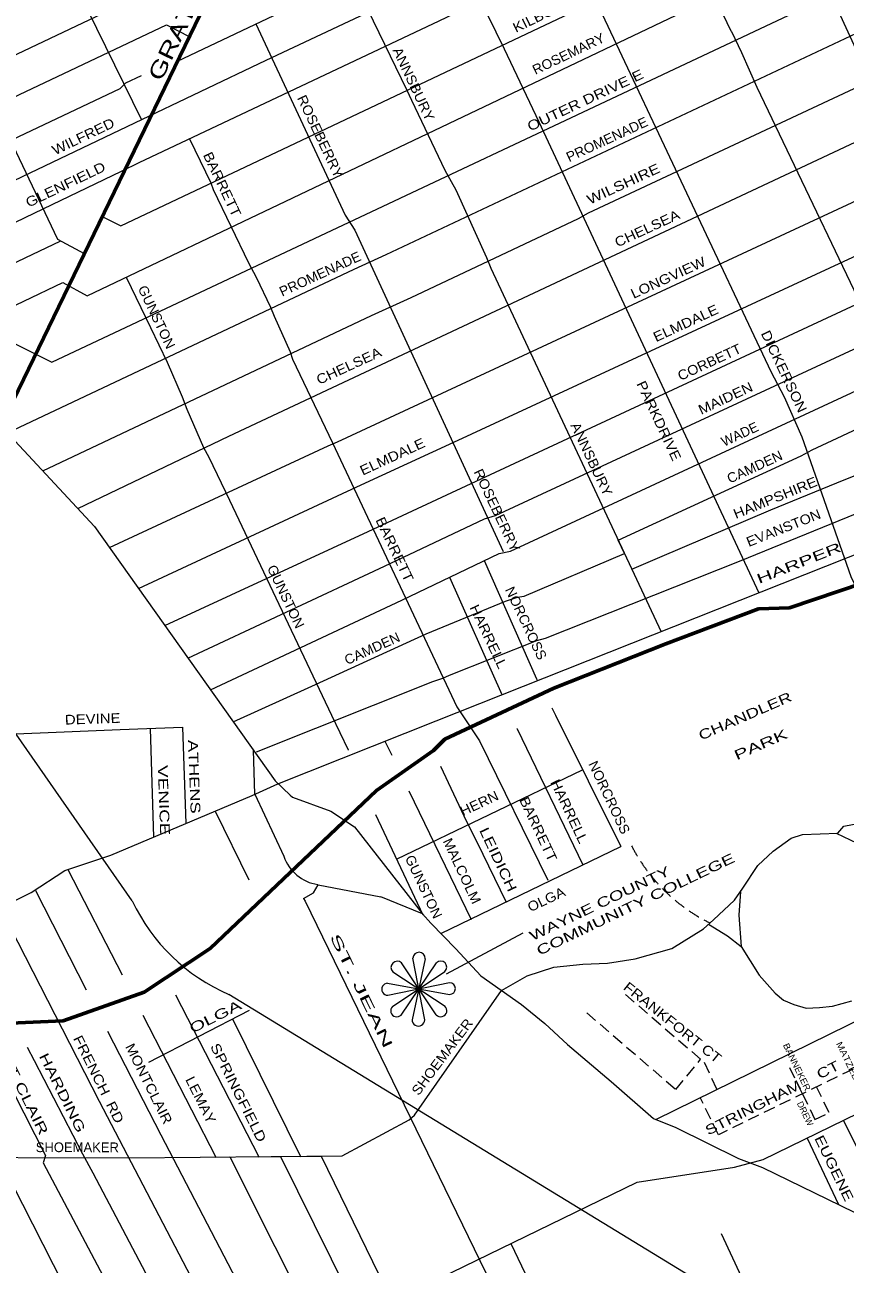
# Model space of a CAD drawing. Extents: x 34705 to 138605, y 34275 to 143551.
# Drawn here: x 113481 to 119808, y 120262 to 129823 of the extents above; entities that cross this region are included whole.
import ezdxf
from ezdxf.enums import TextEntityAlignment as Align

# ---------------------------------------------------------------- set-up
doc = ezdxf.new("R2010")
doc.units = 0
doc.header["$LTSCALE"] = 30
doc.linetypes.add('MEDIUM_DASHED', pattern=[4.5, 3, -1.5])
for name, color, linetype, lineweight in [('1', 7, 'Continuous', 13), ('11', 7, 'Continuous', 13), ('3', 7, 'Continuous', 13), ('50', 7, 'Continuous', 13), ('51', 7, 'Continuous', 35)]:
    doc.layers.add(name, color=color, linetype=linetype, lineweight=lineweight)

msp = doc.modelspace()

# ---------------------------------------------------------------- linework, layer by layer
at = {"layer": '1'}
for p, q in [((116755.42, 125560.55), (117160.43, 124657.18)), ((114448.08, 124395.42), (114473.12, 123556.38)), ((114698.47, 124405.86), (114722.27, 123661.73)), ((116258.49, 124296.27), (116310.6, 124188.4)), ((115254.35, 123887.35), (115244.15, 124226.21)), ((116347.69, 123387.37), (117783.21, 124076.65)), ((116443.32, 123913.7), (116922.95, 122920.93)), ((115254.35, 123887.35), (115479.34, 123408.64)), ((114949.04, 123757.61), (115207.69, 123227.81)), ((116185.04, 123730.28), (116552.13, 122956.37)), ((116690.38, 122813.88), (118077.72, 123484.05)), ((113814.03, 123307.24), (114231.65, 122495.29)), ((113563.24, 123146.07), (113955.21, 122378.93)), ((114437.67, 121821.56), (115213.51, 122222.36)), ((119794.08, 121370.72), (120072.42, 120808.06)), ((119514.23, 121234.18), (119755.76, 120723.33))]:
    msp.add_line(p, q, dxfattribs=at)
at = {"layer": '1', "linetype": 'MEDIUM_DASHED'}
for p, q in [((117815.28, 122201.75), (118503.35, 121608.85)), ((118503.35, 121608.85), (118692.81, 121843.04)), ((119478.21, 121576.44), (119380.52, 121776.68))]:
    msp.add_line(p, q, dxfattribs=at)
at = {"layer": '1', "lineweight": 53}
msp.add_lwpolyline([(101368.9, 103017.54), (102548.84, 105055.11), (103212.24, 106184.42), (103282.07, 106324.13), (104294.63, 108304.78), (105138.43, 110039.49), (106145.17, 112117.65), (109289.05, 118526.78), (110743.87, 121478.11), (113275.26, 126686.61), (116465.7, 133274.74), (120395.18, 141348.71), (121157.51, 142914.61), (121243.66, 143093.14)], dxfattribs=at)
at = {"layer": '1'}
for points in [[(113828.8, 142881.64), (113908.05, 140286.22), (113913.86, 140181.52), (113989.46, 137633.88), (114001.09, 137546.63), (114123.19, 133520.13), (114158.08, 133438.7), (115742.57, 131946.76), (115893.76, 131970.03), (116108.9, 131847.88), (116858.99, 130289.04), (117178.8, 129637.59), (117446.27, 129073.38), (119143.14, 125441.86)], [(112413.12, 135252.27), (112419.49, 134940.82), (112407.87, 134853.57), (112487.81, 132851.23), (112555.76, 132711.83), (112628.32, 132747.22), (112750.93, 132473.15), (113175.4, 131594.85), (113216.1, 131519.24), (113727.8, 130446.09), (113756.87, 130364.66), (114380.05, 129090.06)], [(117019.74, 133007.29), (117040.09, 131765.86), (117934.55, 129905.56), (119235.82, 127149.24), (119336.89, 126952.09), (119473.34, 126643.73), (119851.09, 125566.98), (121478.31, 122254.59), (121549.06, 122178.76), (122869.28, 119400.96), (123384.74, 118354.54), (125383.29, 114242.35)], [(111509.73, 132520.15), (111657.77, 132426.62), (111721.73, 132374.27), (111791.51, 132252.12), (113733.61, 128168.91), (113939.82, 128058.9)], [(111388.95, 128630.48), (111591.31, 128731.69), (112199.45, 129022.83), (113089.94, 129448.66), (113168.13, 129479.08), (114942.6, 130319.89), (115159.79, 130211.26), (115789.65, 130502.39), (119505.83, 132275.26)], [(114657.99, 129541.89), (118932.44, 131571.33), (119006.28, 131601.74), (119653.52, 131910.26), (120250.8, 132205.74), (122306.69, 132245.12)], [(118640.45, 132236.99), (118947.91, 131597.77), (118976.98, 131539.6), (119070.01, 131341.84), (119110.72, 131254.59), (119192.12, 131084.45), (119221.19, 131010.29), (119680.55, 130073.83), (119738.7, 129963.31), (120023.62, 129343.86), (120895.82, 127529.09), (121424.96, 126396.32), (121535.43, 126349.79), (121580.04, 126258.34)], [(117784.51, 132160.52), (118927.56, 129777.18), (118930.46, 129771.37), (119008.96, 129608.5), (119128.16, 129340.94), (120163.17, 127175.74), (120291.09, 126850.01), (120500.42, 126320.7), (120605.09, 126058.96), (120610.9, 125977.53), (120655.3, 125888.69)], [(112840.5, 128350.56), (113029.13, 128444.9), (113463.52, 128653.48), (114330.11, 129066.28), (115342.23, 129548.61), (116835.44, 130253.62), (117564.12, 130602.33), (120368.08, 131927.64), (122067.69, 131958.71)], [(109137.12, 131674.83), (109369.7, 131394.19), (109596.48, 131080.09), (109770.92, 130812.53), (109968.62, 130498.44), (110189.57, 130143.63), (110387.27, 129835.35), (110573.34, 129538.7), (110701.26, 129381.66), (111026.89, 129015.21), (111404.84, 128613.87), (113227.73, 126708.96), (113338.21, 126685.69), (114018.53, 125952.8), (115411.14, 123991.18), (115527.43, 123880.66), (115544.77, 123865.42)], [(112242.46, 127738.56), (112493.21, 127860.75), (113690.88, 128437.04), (114226.55, 128694.85), (114363, 128760.57), (116677.5, 129852.48), (118426, 130690.37), (118552.34, 130735.87), (119936.99, 131403.15), (120376.65, 131620.52), (122075.94, 131656.69)], [(114077.47, 128343.14), (114221.52, 128271.09), (120094.42, 131054.24), (120633.06, 131036.86), (121119.57, 131019.48), (121423.64, 131023.82), (121506.17, 131028.17), (122010.06, 131032.51), (122091.39, 131029.44)], [(115691.04, 130834.8), (116428.71, 129317.68), (116463.59, 129242.06), (116719.44, 128701.12), (116806.66, 128549.89), (117040.69, 128027.86), (117075.58, 127946.42), (118387.98, 125140.52)], [(112662.87, 127299.24), (112868.41, 127402.04), (113774.1, 127835.49), (113960.89, 127732.28), (120307.27, 130758.76), (120750.34, 130741.38), (121167.35, 130719.65), (121393.23, 130715.31), (122101.59, 130718.5)], [(117156.53, 122373.91), (117354.34, 122487.31), (117562.04, 122553.07), (117785.51, 122576.74), (117974.81, 122584.64), (118187.76, 122618.83), (118471.9, 122697.65), (118716.31, 122849), (118791.96, 122918.86), (118954.9, 123070.21), (119018.91, 123163.34), (119135.3, 123337.98), (119251.69, 123448.58), (119391.35, 123547.54), (119478.64, 123576.65), (119752.14, 123588.29), (119798.7, 123640.68), (119973.28, 123675.61), (120118.76, 123757.1), (125265.94, 126298.05), (133709.74, 130483.48)], [(112854.63, 127098.85), (113375.55, 127377.06), (113688.31, 127220.63), (120428.89, 130395.93), (122118.66, 130309.03), (123063.45, 129791.94), (123162.27, 127218.46), (123379.46, 126788.28)], [(113348.12, 126675.01), (116020.97, 127937.6), (116268.57, 128050.57), (120507.08, 130048.31), (121532.24, 129996.17), (122123, 129922.3), (122867.97, 129505.15), (123074.46, 129505.15)], [(111601.27, 128408.6), (111804.16, 128510.08), (114573.37, 129822.36), (114749.79, 129731.45)], [(115262.39, 129828.85), (115951.9, 128355.04), (116027.49, 128238.71), (117171.66, 125760.32)], [(113620.9, 126381.15), (116155.63, 127581.28), (116459.7, 127720.33), (117750.9, 128328.67), (117829.09, 128372.12), (120724.28, 129726.76), (120767.72, 129731.11), (121532.24, 129692), (122132.49, 129621.36)], [(97901.79, 110686.48), (98842.55, 111139.22), (98862.73, 111098.07), (107780.39, 115477.93), (107908.41, 115576.89), (108065.53, 115629.28), (109209.03, 116179.38), (109744.4, 116470.44), (111059.56, 117168.98), (111717.14, 117524.08), (112237.97, 117804.95), (112528.94, 117956.3), (112895.56, 118183.33), (114356.2, 118957.54), (115440.05, 119549.85), (118204.21, 120894.54), (118954.9, 121010.96), (119176.03, 121069.18), (124515.25, 123674.15), (127785.69, 125298.26), (131565.33, 127169.77), (132886.31, 127821.74), (134611.73, 128667.27), (136181.01, 129472.15)], [(111812.18, 128188.2), (112021.35, 128292.82), (114217.17, 129331.34), (114260.61, 129374.79), (114382.24, 129431.28)], [(113889.29, 126092.03), (115055.54, 126649.23), (120896.94, 129393.26), (120909.98, 129436.72), (122144.83, 129313.63)], [(114134.53, 125789.4), (115820.06, 126575.36), (115893.91, 126605.77), (121183.64, 129067.37), (122156.67, 129018.7)], [(114750.34, 128943.31), (114916.89, 128603.7), (114934.34, 128551.35), (115207.62, 127987.14), (115265.77, 127876.63), (115376.25, 127643.96), (115405.32, 127574.16), (115527.43, 127300.79), (115544.88, 127242.62), (115853.05, 126596.98), (116812.47, 124561.2), (116986.91, 124299.46), (117516.05, 123223.39)], [(114358.82, 125473.48), (116041.6, 126258.15), (116823.49, 126618.81), (121353.05, 128719.75), (121587.62, 128698.02), (122121.91, 128724.09), (122217.48, 128741.47), (124206.86, 128816.28)], [(115267.3, 124213.7), (116626.93, 124756.86), (116705.12, 124782.93), (116757.25, 124804.66), (117430.55, 125074.07), (117495.7, 125091.45), (118992.16, 125685.66), (120473.15, 126288.7), (122030.69, 126904.51), (122195.76, 126974.03), (124530.58, 127886.54), (124621.81, 127925.65), (126181.25, 128412.32), (126237.72, 128442.74), (126774.51, 128701.62)], [(114560.02, 125190.06), (116128.47, 125914.87), (116962.5, 126301.6), (121448.61, 128389.51), (122182.63, 128371.71)], [(112450.16, 127521.52), (112655.56, 127632.34), (113759.25, 128155.23)], [(114913.21, 124692.56), (116389.11, 125384.75), (117140.6, 125745.41), (117227.47, 125762.79), (121622.37, 127802.89), (121717.93, 127863.73), (122178.38, 128085.34), (123838.82, 128141.82), (124181.99, 128146.17), (124529.5, 128159.21), (124616.37, 128167.9), (125128.95, 128176.59), (125437.36, 128185.28)], [(108436.9, 121413.01), (109494.34, 121968.63), (109634.95, 122036.15), (111021.43, 122424.37), (111122.67, 122413.12), (111499.52, 122480.64), (112180.11, 122643.81), (112478.21, 122722.58), (112743.97, 122776.02), (112884.59, 122809.78), (113267.07, 123001.08), (113531.43, 123130.49), (113790.16, 123299.29), (114144.51, 123417.44), (115235.7, 123878.81), (115432.56, 123968.84), (116653.11, 124452.72), (124173.08, 127439.91), (124643.06, 127626.95), (126069.8, 128061.11)], [(114738.96, 124938.01), (116254.45, 125645.47), (117027.65, 126010.47), (117110.19, 126036.54), (121524.64, 128086.42)], [(114262.97, 127876.34), (114451.72, 127486.92), (114579.64, 127219.35), (114695.93, 126951.79), (114730.82, 126858.73), (114858.74, 126562.08), (114899.45, 126486.47), (115059.36, 126156.38), (115847.24, 124497.22), (115975.16, 124229.66), (115975.49, 124227.34)], [(115088.43, 124445.74), (115694.09, 124719.92), (116575.89, 125124.03), (117188.38, 125376.06), (117280.68, 125406.48), (117332.81, 125415.17), (118105.73, 125743.96), (118057.85, 125846.34), (119469.99, 126497.14), (119552.52, 126543.85), (121739.65, 127563.9), (121813.5, 127611.7), (122205.52, 127801.17)], [(118346.91, 121379.51), (124443.96, 124372.69), (124590.9, 124476.02), (131269.97, 127786.78)], [(118161.62, 125624.47), (118379.68, 125716.08), (119235.42, 126081.08), (119800.12, 126311.38), (121230.23, 126879.03), (122221.82, 127282.55)], [(111762.44, 126050.24), (112274.13, 125363.89), (112811.98, 124651.35), (112849.78, 123927.2), (113291.7, 123043.08), (113314.95, 122967.46), (114053.42, 121519.14), (116755.93, 116340.18)], [(117024.92, 125689.89), (117428.83, 124776.41), (117435.99, 124762.66)], [(117544.88, 124553.53), (117574.2, 124497.22), (118077.72, 123484.05)], [(112117.66, 124304.76), (112791.96, 124331.53), (112915.16, 124331.53), (114216.23, 124385.76), (114698.47, 124405.86)], [(117276.9, 124394.2), (117277.65, 124392.52), (117784.78, 123342.54)], [(116686.71, 124103.61), (116888.06, 123677.08), (116969.47, 123514.22), (117190.43, 123060.53)], [(115544.77, 123865.42), (115840.84, 123757.6), (116023.1, 123635.96), (116547.19, 122963.87), (116225.77, 123094.95)], [(119738.12, 123587.69), (119901.51, 123509.86), (119988.73, 123457.51), (120087.58, 123352.81), (120180.62, 123224.85), (120285.28, 123021.27), (120331.8, 122806.06), (120325.98, 122742.08)], [(115631.77, 123084.32), (115708.82, 123125.83), (115742.7, 123189.57), (116225.77, 123094.95)], [(115631.77, 123084.32), (115642.27, 123061.99), (121617.28, 110770.39)], [(119001, 123136.46), (118987.45, 122953.47), (119006.05, 122712.99)], [(116547.19, 122963.87), (116613.32, 122893.31), (116805.2, 122695.54), (116997.09, 122486.15), (117311.08, 122265.12), (117491.33, 122119.7), (117665.77, 121956.84), (118003.03, 121671.83), (118328.65, 121386.82), (118503.09, 121317.02), (118985.7, 121078.54), (119171.77, 121008.74), (120379.77, 120418.37), (120967.05, 119644.76)], [(118755.23, 122884.94), (118901.39, 122794.42), (119006.05, 122712.99), (119145.6, 122491.96), (119267.71, 122352.37), (119331.67, 122300.02), (119413.08, 122265.12), (119506.11, 122236.03), (119610.78, 122241.85), (119709.63, 122253.48), (119860.81, 122294.2)], [(110898.74, 121088.09), (112569.67, 121088.09), (114286.37, 121082.27), (115928.87, 121096.83), (116446.78, 121376.24), (116487.52, 121411.17), (117156.53, 122373.91)], [(114643.86, 122339.84), (115286.41, 121091.13), (115453.06, 121092.61), (117537.85, 116881.91), (117578.55, 116788.85), (119695.09, 112413.35), (119747.43, 112308.65)], [(114392, 122183.52), (114955.37, 121088.2), (115063.4, 121089.16), (115757.37, 119708.21)], [(115082.68, 122154.76), (115607.11, 121093.98), (115765.73, 121095.38), (116310.96, 119976.31), (116363.29, 119877.43), (117113.38, 118336.04), (117798.89, 116979.24)], [(114118.64, 122060.38), (114530.22, 121258.85), (115403.87, 119580.78), (117000.35, 116492.9), (116968.79, 116473.73), (116930.86, 116449.93), (119190.33, 112040.04), (119249.32, 112077.95), (120257.44, 110107.32)], [(112894.44, 121929.17), (113280.07, 121136.71), (113303.32, 121037.82), (114332.52, 119016.58), (114384.85, 118935.14), (115124.76, 117466.47), (115153.84, 117385.04), (115915.56, 115866.92), (115979.52, 115808.75), (118244.33, 111511.78), (118360.62, 111453.62), (119805.57, 108692.21)], [(113220.39, 121920.32), (113640.58, 121101.81), (113623.13, 121043.64), (114618.89, 119164.9), (116241.18, 116041.41), (116281.88, 115983.25), (117113.38, 114415.69), (118526.35, 111686.28), (118604.84, 111577.22), (119553.33, 109764.96)], [(113499.83, 121937.03), (113553.36, 121834.69), (113925.49, 121113.44), (114006.9, 120968.02), (116520.26, 116192.32), (116594.39, 116238.83), (118853.58, 111823.61), (118799.46, 111788.83), (119797.02, 109882.81)], [(118851.97, 120498.34), (119008.96, 120160.98), (119749.65, 118638.14)], [(117229.8, 120421.68), (117585.07, 119678.93), (117625.68, 119634.85), (118636.88, 117539.82)]]:
    msp.add_lwpolyline(points, dxfattribs=at)
at = {"layer": '1', "linetype": 'MEDIUM_DASHED'}
for points in [[(118113.7, 122342.87), (118720.62, 121819.72), (118818.01, 121611.27)], [(121082.25, 122359.04), (118830.23, 121260.3), (118690.32, 121547.06)], [(119478.21, 121576.44), (119574.69, 121378.69), (119684.06, 121432.05), (119587.57, 121629.8)]]:
    msp.add_lwpolyline(points, dxfattribs=at)
msp.add_arc((119362.03, 124105.9), 1350.27, 207.20903, 243.78591, dxfattribs=at)
at = {"layer": '1'}
msp.add_arc((115786.71, 123512.04), 324.29, 198.59424, 261.80515, dxfattribs=at)
at = {"layer": '3'}
for p, q in [((117322.43, 122814.43), (116730.95, 122498.67)), ((117322.43, 122814.43), (116730.95, 122498.67)), ((116383.36, 122183.87), (116655.8, 122587.15)), ((116383.36, 122183.87), (116655.8, 122587.15)), ((116653.09, 122185.28), (116386.44, 122585.64)), ((116653.09, 122185.28), (116386.44, 122585.64)), ((116386.88, 122584.64), (116387.6, 122585.36)), ((116386.88, 122584.64), (116387.6, 122585.36)), ((116569.34, 122618.35), (116467.81, 122148.02)), ((116569.34, 122618.35), (116467.81, 122148.02)), ((116565.79, 122147.71), (116473.27, 122623.73)), ((116565.79, 122147.71), (116473.27, 122623.73)), ((116316.06, 122249.76), (116721.27, 122519.65)), ((116316.06, 122249.76), (116721.27, 122519.65)), ((116318.83, 122517.66), (116721.92, 122253.64)), ((116318.83, 122517.66), (116721.92, 122253.64)), ((116319.46, 122516.64), (116320.19, 122517.38)), ((116319.46, 122516.64), (116320.19, 122517.38)), ((116279.07, 122429.19), (116756.96, 122342.49)), ((116279.07, 122429.19), (116756.96, 122342.49)), ((116280.04, 122336.96), (116756.02, 122434.12)), ((116280.04, 122336.96), (116756.02, 122434.12))]:
    msp.add_line(p, q, dxfattribs=at)
for centre, radius, start, end in [((116521.14, 122620.09), 48.1, 357.90544, 177.31124), ((116521.14, 122620.09), 48.1, 357.90544, 177.31124), ((116353.38, 122551.33), 48.02, 45.54578, 225.33734), ((116353.38, 122551.33), 48.02, 45.54578, 225.33734), ((116688.5, 122553.3), 46.65, 314.26963, 133.99655), ((116688.5, 122553.3), 46.65, 314.26963, 133.99655), ((116279.4, 122383.16), 45.88, 90.42817, 271.25269), ((116279.4, 122383.16), 45.88, 90.42817, 271.25269), ((116756.88, 122388.41), 45.43, 270.57171, 90.10109), ((116756.88, 122388.41), 45.43, 270.57171, 90.10109), ((116756.88, 122388.41), 45.43, 270.54777, 270.57171), ((116756.88, 122388.41), 45.43, 270.54777, 270.57171), ((116349.74, 122217.03), 46.64, 135.13004, 315.42051), ((116349.74, 122217.03), 46.64, 135.13004, 315.42051), ((116687.92, 122218.71), 48.38, 224.62256, 46.0351), ((116687.92, 122218.71), 48.38, 224.62256, 46.0351), ((116516.68, 122147.77), 48.9, 178.86395, 0.59288), ((116516.68, 122147.77), 48.9, 178.86395, 0.59288)]:
    msp.add_arc(centre, radius, start, end, dxfattribs=at)
at = {"layer": '50'}
for p, q in [((114310.06, 123063.91), (112665.98, 125417.47)), ((118804.69, 120050.59), (115055.23, 122343.49))]:
    msp.add_line(p, q, dxfattribs=at)
msp.add_arc((115633.79, 123687.52), 1463.26, 205.22512, 246.70955, dxfattribs=at)
at = {"layer": '51', "lineweight": 60}
msp.add_lwpolyline([(107292.97, 119950.63), (110456.13, 121661.99), (111429.48, 121939.01), (111860.26, 122053.92), (113776.21, 122140.11), (114400.84, 122360.69), (114909.57, 122697.22), (116193.7, 123916.11), (116632.69, 124223.91), (116719.86, 124312.14), (117560.91, 124706.13), (118426.27, 125047.42), (119140.77, 125316.55), (119378.93, 125325.38), (119948.67, 125518.72), (120494.32, 125699.29), (120946.63, 125836.77), (121127.15, 125840.88), (124848.27, 127379.88), (125296.48, 127513.25), (126067.79, 127812.85), (126510.87, 128132.96), (126896.53, 128613.13), (127118.07, 128867.57)], dxfattribs=at)

# ---------------------------------------------------------------- texts
at = {"layer": '11'}
for s, height, rotation, width, p in [('GRATIOT', 120, 64.201, 1.4, (114750.53, 129828.57)), ('KILBOURNE', 75, 25.863, 1.15, (117568.2, 129905.32)), ('ROSEMARY', 75, 25.479, 1.05, (117690.36, 129565.36)), ('ANNSBURY', 75, 295.199, 1.1, (116446.16, 129349.36)), ('OUTER DRIVE E', 75, 25.224, 1.25, (117819.63, 129206.93)), ('ROSEBERRY', 75, 295.199, 1.1, (115726.12, 128945.35)), ('WILFRED', 75, 25.649, 1.15, (113948.35, 128927.69)), ('PROMENADE', 75, 24.774, 1.05, (117986.84, 128905.16)), ('BARRETT', 75, 295.396, 1.15, (114969.08, 128576.02)), ('GLENFIELD', 75, 25.696, 1.2, (113811.16, 128556.66)), ('WILSHIRE', 75, 24.774, 1.25, (118113.17, 128561.16)), ('CHELSEA', 75, 24.774, 1.15, (118296.58, 128217.87)), ('PROMENADE', 75, 24.774, 1.05, (115773.98, 127867.07)), ('LONGVIEW', 75, 24.773, 1.15, (118458.51, 127838.5)), ('GUNSTON', 75, 295.403, 1.05, (114463.81, 127552.03)), ('ELMDALE', 75, 24.773, 1.15, (118593.82, 127487.15)), ('DICKERSON', 75, 295.272, 1.15, (119302.63, 127132.7)), ('CORBETT', 75, 24.958, 1.1, (118777, 127186.19)), ('CHELSEA', 75, 24.774, 1.15, (115995.83, 127157.56)), ('PARKDRIVE', 75, 295.045, 1.15, (118337.75, 126752.1)), ('MAIDEN', 75, 24.908, 1.15, (118900.63, 126908.03)), ('ANNSBURY', 75, 295.199, 1.1, (117818.13, 126456.03)), ('ELMDALE', 75, 24.773, 1.15, (116331.53, 126457.48)), ('CAMDEN', 75, 24.748, 1.05, (119125.81, 126378.55)), ('ROSEBERRY', 75, 295.199, 1.1, (117087.98, 126061.57)), ('HAMPSHIRE', 75, 22.187, 1.15, (119282.25, 126139.81)), ('BARRETT', 75, 295.396, 1.15, (116299.47, 125760.23)), ('EVANSTON', 75, 21.72, 1.1, (119346.36, 125906.55)), ('HARPER', 75, 21.624, 1.65, (119464.46, 125636.18)), ('GUNSTON', 75, 295.403, 1.05, (115460.42, 125395.86)), ('NORCROSS', 75, 295.206, 1.05, (117312.97, 125191.19)), ('HARRELL', 75, 295.204, 1.15, (117022.81, 125087.55)), ('CAMDEN', 75, 24.371, 1.05, (116174.97, 124977.08)), ('CHANDLER', 75, 23.665, 1.4, (119051.17, 124456.17)), ('DEVINE', 75, 1.947, 1.15, (114005.94, 124431.43)), (' PARK', 75, 23.665, 1.6, (119151.52, 124227.19)), ('ATHENS   ', 75, 272.18, 1.4, (114752.48, 123962.47)), ('VENICE    ', 75, 272.03, 1.45, (114519.11, 123758.74)), ('NORCROSS', 75, 295.206, 1.05, (117954.89, 123846.68)), ('HARRELL', 75, 295.204, 1.15, (117645.92, 123739.94)), ('HERN', 75, 25.208, 1.1, (117001.67, 123783.08)), ('BARRETT', 75, 295.203, 1.15, (117407.34, 123601.65)), ('LEIDICH', 75, 295.207, 1.35, (117098.01, 123367.99)), ('MALCOLM', 75, 295.205, 1.1, (116818.85, 123279.35)), ('GUNSTON', 75, 295.204, 1.05, (116523.33, 123157.71)), ('OLGA', 75, 25.205, 1.1, (117519.4, 123042.33)), ('ST. JEAN', 75, 296.013, 2.2, (116043.15, 122354.63)), ('FRANKFORT CT', 75, 321.4, 1.2, (118453.64, 122097.37)), ('OLGA      ', 75, 26.594, 1.55, (115083.78, 122196.64)), ('SHOEMAKER', 75, 52.998, 1.1, (116730.02, 121838.76)), ('FRENCH  RD', 75, 296.454, 1.2, (114016.97, 121671.85)), ('MONTCLAIR', 75, 296.453, 1.15, (114404.3, 121637.48)), ('SPRINGFIELD', 75, 296.454, 1.25, (115094.91, 121569.22)), ('BANNEKER', 49.21, 295.848, 1.1, (119413.85, 121772.89)), ('MATZELIGER', 49.21, 295.848, 1.2, (119846.49, 121736.44)), ('ST.CLAIR   ', 75, 296.453, 1.5, (113475.97, 121497.49)), ('HARDING   ', 75, 296.453, 1.45, (113764.69, 121513.51)), ('STRINGHAM    CT', 75, 26.73, 1.35, (119262.58, 121511.5)), ('LEMAY', 75, 296.454, 1.15, (114804.03, 121512.31)), ('EUGENE  ', 75, 295.852, 1.3, (119704.62, 120953.98))]:
    msp.add_text(s, height=height, rotation=rotation, dxfattribs=dict(at, width=width)).set_placement(p, align=Align.CENTER)
for s, height, rotation, p in [('WADE', 75, 24.901, (119010.68, 126630.64)), ('DREW', 49.21, 295.848, (119477.71, 121412.54)), ('SHOEMAKER', 75, 359.951, (113886.05, 121126.45))]:
    msp.add_text(s, height=height, rotation=rotation, dxfattribs=at).set_placement(p, align=Align.CENTER)
for s, width, p in [('COMMUNITY COLLEGE', 1.5, (117449.99, 122641.13)), ('WAYNE COUNTY', 1.45, (117395.85, 122753.8))]:
    msp.add_text(s, height=75, rotation=25.665, dxfattribs=dict(at, width=width)).set_placement(p)

doc.saveas('drawing.dxf')
